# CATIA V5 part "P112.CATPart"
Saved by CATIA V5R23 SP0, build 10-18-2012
Part number: P112
Definition: support plateau
Bounding box of the stored display mesh (mm): x -28 to 28, y -28 to 28, z 0 to 44
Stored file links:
  C:\wamp\www\COURS\CONCEPTION GMP1\TITRE 02-SEMESTRE 2\03-TP7-PRESSE MECANIQUE\eleve\P112.CATPart
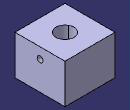
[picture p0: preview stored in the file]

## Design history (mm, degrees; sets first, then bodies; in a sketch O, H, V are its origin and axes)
Body1 (main body)
  Sketch1 on xy-plane, origin (0, 0, 0), H (1, 0, 0), V (0, 1, 0)
    line L1 (-28, 28) -> (28, 28)
    line L2 (28, 28) -> (28, -28)
    line L3 (28, -28) -> (-28, -28)
    line L4 (-28, -28) -> (-28, 28)
    length L2 = 56
    length L1 = 56
    horizontal: L1 H, L3 H
    vertical: L2 V, L4 V
    symmetry: L2 L4 V, L1 L3 H
  Pad1: profile Sketch1, direction (0, 0, 1), length 44
  Sketch2 on zx-plane, origin (0, 0, 0), H (-1, 0, 0), V (0, 0, 1)
    point P1 (-10, 44)
    line L1 (-10, 44) -> (-10, 14)
    point P2 (-10, 14)
    line L2 (-10, 14) -> (-3, 10)
    point P3 (-3, 10)
    line L3 (-3, 10) -> (-3, 0)
    point P4 (-3, 0)
    distance P1 H = 44
    distance P2 P3 V = 4
    length L1 = 30
    distance L3 V = 3
    distance L1 V = 10
    vertical: L1 V, L3 V
    coincidence: P4 H
  Groove1: profile Sketch2, axis Sketch2.V, angle 360
  Sketch3 on face of Pad1, origin (28, -1.2296, 27.2162), H (0, 1, 0), V (0, 0, 1)
    point P1 (1.2296, 4.7838)
    reference intersected line E1 through (1.2296, 0) direction (0, 1) from zx-plane
    reference projected line E2 (-26.7704, 16.7838) -> (29.2296, 16.7838) from edge [face of Pad1 | face of Pad1]
    distance P1 E2 = 12
    coincidence: P1 E1
  Hole1: placed by Sketch3, at (28, 0, 32) direction (-1, 0, 0), diameter 6.647, through (limit type 6), threaded "M8", thread diameter 8, thread depth 10, pitch 1.25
